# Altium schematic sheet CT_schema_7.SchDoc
size 209 x 185 mm
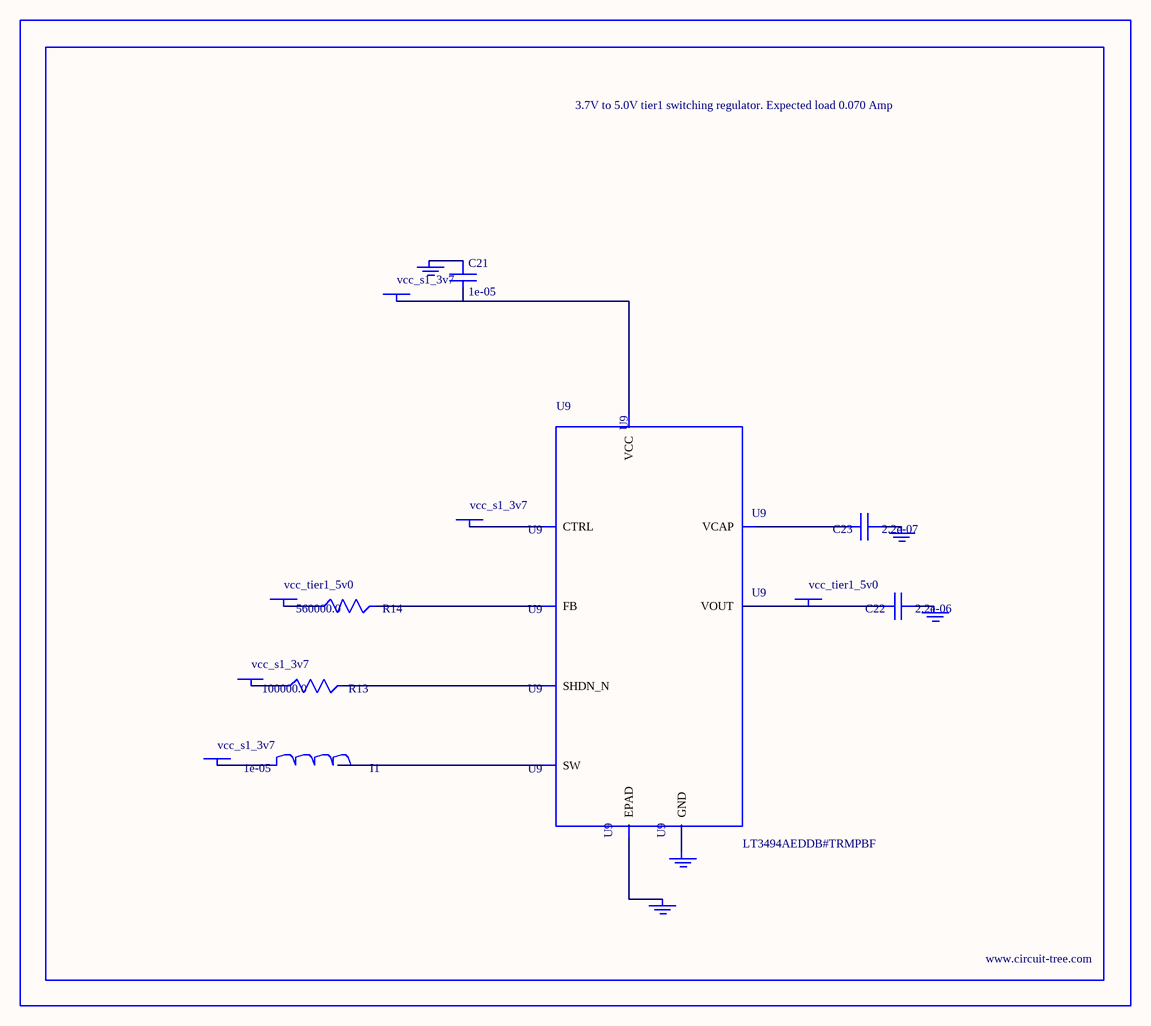
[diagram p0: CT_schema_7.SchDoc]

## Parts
BORDER6  (no value)
C21  1e-05  [C1210]
C22  2.2e-06  [C0603]
C23  2.2e-07  [C0603]
GND_INSTANCE_6_0  (no value)
GND_INSTANCE_6_1  (no value)
GND_INSTANCE_6_2  (no value)
GND_INSTANCE_6_3  (no value)
GND_INSTANCE_6_4  (no value)
I1  1e-05  [L1210]
POWER_INSTANCE_6_0  vcc_s1_3v7
POWER_INSTANCE_6_1  vcc_s1_3v7
POWER_INSTANCE_6_2  vcc_s1_3v7
POWER_INSTANCE_6_3  vcc_s1_3v7
POWER_INSTANCE_6_4  vcc_tier1_5v0
POWER_INSTANCE_6_5  vcc_tier1_5v0
R13  100000.0  [R0603]
R14  560000.0  [R0603]
U9  LT3494AEDDB#TRMPBF  [DFN-8_DDB]

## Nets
NetC21_1: C21.1 GND_INSTANCE_6_0.0(GND)
NetC21_2: C21.2 POWER_INSTANCE_6_1.0(PWR) U9.3(VCC)
NetC22_1: C22.1 GND_INSTANCE_6_1.0(GND)
NetC22_2: C22.2 POWER_INSTANCE_6_5.0(PWR) U9.7(VOUT)
NetC23_1: C23.1 GND_INSTANCE_6_2.0(GND)
NetC23_2: C23.2 U9.8(VCAP)
NetGND_INSTANCE_6_3_0: GND_INSTANCE_6_3.0(GND) U9.9(EPAD)
NetGND_INSTANCE_6_4_0: GND_INSTANCE_6_4.0(GND) U9.2(GND)
NetI1_1: I1.1 POWER_INSTANCE_6_0.0(PWR)
NetI1_2: I1.2 U9.1(SW)
NetPOWER_INSTANCE_6_2_0: POWER_INSTANCE_6_2.0(PWR) U9.4(CTRL)
NetPOWER_INSTANCE_6_3_0: POWER_INSTANCE_6_3.0(PWR) R13.1
NetPOWER_INSTANCE_6_4_0: POWER_INSTANCE_6_4.0(PWR) R14.1
NetR13_2: R13.2 U9.5(SHDN_N)
NetR14_2: R14.2 U9.6(FB)

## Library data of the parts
BORDER6 = BORDER_PAGE6
C21 = C1210C106K5PACTU
C22 = GRM188R61H225KE1115D
C23 = C0603C224K3RAC
GND_INSTANCE_6_0-GND_INSTANCE_6_4 = GND
I1 = CBC3225T100MR
POWER_INSTANCE_6_0-POWER_INSTANCE_6_5 = PWR
R13 = RC0603JR-07100KL
R14 = RC0603JR-07560KL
